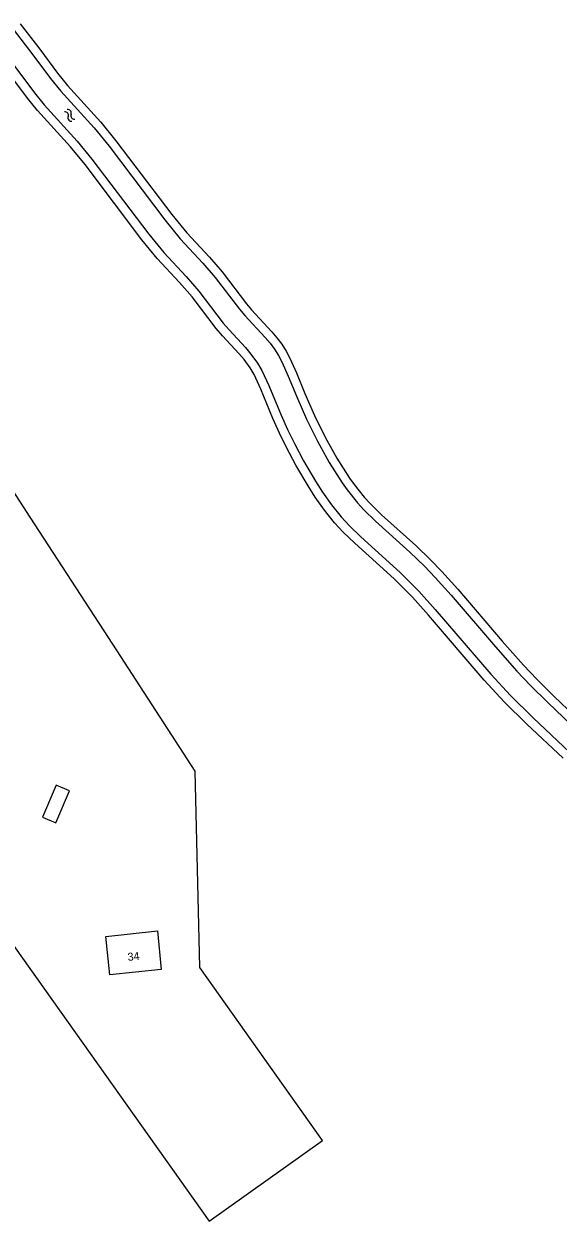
# Model space of a CAD drawing. Extents: x 126000 to 131009, y 393000 to 395500.
# Drawn here: x 129078 to 129144.8, y 395080.5 to 395230 of the extents above; entities that cross this region are included whole.
import ezdxf

# ---------------------------------------------------------------- set-up
doc = ezdxf.new("R2010")
doc.units = 0
for name, color, linetype in [('gg-anno-huisnummerreeks BGT', 7, 'Continuous'), ('gg-bbg-bijgebouw', 7, 'Continuous'), ('gg-bbg-hoofdgebouw', 7, 'Continuous'), ('gg-kntw-bovenkant insteek waterloop', 7, 'Continuous'), ('gg-kntw-waterlijn', 7, 'Continuous'), ('gt-grn-vlakafsluiter', 7, 'Continuous'), ('gt-symb-watersymbool', 7, 'Continuous')]:
    doc.layers.add(name, color=color, linetype=linetype)

# ---------------------------------------------------------------- blocks, each defined once
blk = doc.blocks.new('gt0-WA')
at = {"layer": 'gt-symb-watersymbool'}
for centre, start, end in [((-0.32, 0.02), 28.0725, 151.9275), ((0.43, 0.42), 208.0725, 331.9275), ((-0.32, -0.43), 28.0725, 151.9275), ((0.43, -0.03), 208.0725, 331.9275)]:
    blk.add_arc(centre, 0.425, start, end, dxfattribs=at)

msp = doc.modelspace()

# ---------------------------------------------------------------- linework, layer by layer
at = {"layer": 'gg-bbg-bijgebouw'}
msp.add_lwpolyline([(129080.32, 395130.92), (129082, 395130.21), (129083.69, 395134.21), (129082.01, 395134.92), (129080.32, 395130.92)], dxfattribs=at)
at = {"layer": 'gg-bbg-hoofdgebouw'}
msp.add_lwpolyline([(129088.76, 395111.2), (129088.24, 395116.02), (129094.68, 395116.71), (129095.14, 395111.89), (129088.76, 395111.2)], dxfattribs=at)
at = {"layer": 'gg-kntw-bovenkant insteek waterloop'}
for points in [[(129077.54, 395230.04), (129079.99, 395226.87), (129082.2, 395223.9), (129083.45, 395222.34), (129087.61, 395217.78), (129089.5, 395215.45), (129096.48, 395206.24), (129098.38, 395203.92), (129101.2, 395200.88), (129102.78, 395199.06), (129105.82, 395195.08), (129106.46, 395194.31), (129109, 395191.58), (129109.64, 395190.82), (129110.25, 395190.01), (129110.77, 395189.17), (129111.24, 395188.29), (129112.06, 395186.46), (129113.11, 395183.86), (129114.33, 395181.11), (129115.67, 395178.42), (129117.13, 395175.8), (129118.71, 395173.3), (129119.28, 395172.48), (129120.53, 395170.92), (129121.28, 395170.11), (129122.71, 395168.71), (129127.01, 395164.85), (129128.85, 395163.08), (129130.23, 395161.63), (129132.23, 395159.39), (129137.78, 395152.92), (129140.44, 395149.93), (129142.13, 395148.15), (129144.27, 395146.05), (129157.74, 395133.17)], [(129145.42, 395138.29), (129140.89, 395142.53), (129138.05, 395145.35), (129135.56, 395148.05), (129128.58, 395156.15), (129126.58, 395158.39), (129124.29, 395160.72), (129119.37, 395165.16), (129117.92, 395166.54), (129116.82, 395167.72), (129115.57, 395169.27), (129114.42, 395170.91), (129113.52, 395172.32), (129112.01, 395174.92), (129110.84, 395177.12), (129109.97, 395178.91), (129109.14, 395180.73), (129107.63, 395184.4), (129106.78, 395186.22), (129106.28, 395187.07), (129105.52, 395188.11), (129104.87, 395188.87), (129102.82, 395191.07), (129102.05, 395191.97), (129099.02, 395195.95), (129097.47, 395197.73), (129094.66, 395200.75), (129092.76, 395203.07), (129085.64, 395212.48), (129083.83, 395214.69), (129079.7, 395219.21), (129078.46, 395220.77), (129073.06, 395227.9)]]:
    msp.add_lwpolyline(points, dxfattribs=at)
at = {"layer": 'gg-kntw-waterlijn'}
for points in [[(129076.66, 395229.39), (129079.11, 395226.2), (129081.33, 395223.23), (129082.61, 395221.63), (129086.78, 395217.06), (129088.64, 395214.77), (129095.61, 395205.56), (129097.55, 395203.19), (129100.38, 395200.14), (129101.93, 395198.36), (129104.96, 395194.4), (129105.63, 395193.59), (129108.17, 395190.85), (129108.78, 395190.14), (129109.34, 395189.39), (129109.82, 395188.62), (129110.25, 395187.81), (129111.04, 395186.03), (129112.1, 395183.43), (129113.33, 395180.65), (129114.69, 395177.91), (129116.18, 395175.24), (129117.79, 395172.69), (129118.4, 395171.82), (129119.69, 395170.2), (129120.49, 395169.34), (129121.96, 395167.91), (129126.26, 395164.05), (129128.07, 395162.3), (129129.42, 395160.88), (129131.4, 395158.66), (129136.96, 395152.2), (129139.63, 395149.18), (129141.35, 395147.38), (129143.5, 395145.26), (129157.01, 395132.35)], [(129073.96, 395228.54), (129079.32, 395221.44), (129080.54, 395219.92), (129084.67, 395215.41), (129086.5, 395213.16), (129093.62, 395203.75), (129095.49, 395201.48), (129098.29, 395198.47), (129099.88, 395196.64), (129102.91, 395192.66), (129103.64, 395191.8), (129105.69, 395189.6), (129106.39, 395188.79), (129107.2, 395187.67), (129107.75, 395186.73), (129108.63, 395184.84), (129110.15, 395181.17), (129110.96, 395179.38), (129111.82, 395177.62), (129112.97, 395175.45), (129114.46, 395172.89), (129115.33, 395171.52), (129116.45, 395169.93), (129117.65, 395168.44), (129118.71, 395167.31), (129120.12, 395165.96), (129125.05, 395161.51), (129127.38, 395159.14), (129129.4, 395156.88), (129136.38, 395148.79), (129138.84, 395146.11), (129141.65, 395143.32), (129146.22, 395139.05)]]:
    msp.add_lwpolyline(points, dxfattribs=at)
at = {"layer": 'gt-grn-vlakafsluiter'}
msp.add_lwpolyline([(129056.36, 395165.34), (129065.87, 395151.44), (129055.55, 395130.22), (129069.19, 395111.04), (129075.99, 395115.87), (129101.17, 395080.45), (129115.35, 395090.53), (129099.98, 395112.15), (129099.42, 395136.68), (129089.1, 395152.55), (129078.78, 395168.41), (129071.44, 395179.69), (129055.12, 395167.31)], dxfattribs=at)

# ---------------------------------------------------------------- block references
at = {"layer": 'gt-symb-watersymbool', "rotation": -51.17017509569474}
msp.add_blockref('gt0-WA', (129083.68, 395218.65), dxfattribs=at)

# ---------------------------------------------------------------- texts
at = {"layer": 'gg-anno-huisnummerreeks BGT'}
msp.add_text('34', height=1, rotation=6.2, dxfattribs=at).set_placement((129091.02, 395112.95))

doc.saveas('drawing.dxf')
